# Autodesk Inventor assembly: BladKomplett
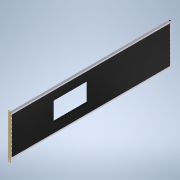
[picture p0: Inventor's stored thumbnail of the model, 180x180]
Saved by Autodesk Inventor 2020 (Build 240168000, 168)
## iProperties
Created: 2019-06
Part Number: BladKomplett
Document SubType Name: Assembly
Designer: cl
Author: cl
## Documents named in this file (4)
- G:\AutoCad\Carl Lund\4-delad\4-Del-0Glas-In\Parts\BladKomplett.iam
- G:\AutoCad\Carl Lund\4-delad\4-Del-0Glas-In\Parts\Blad.ipt
- G:\AutoCad\Carl Lund\4-delad\4-Del-0Glas-In\Parts\AluKarmBlad.ipt
- G:\AutoCad\Carl Lund\4-delad\4-Del-0Glas-In\Styrande(4-Del-0Glas-In).iam
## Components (2 placed, 2 different names)
1. Blad:1 — Flush:1, Flush:2
2. AluKarmBlad:1 — Flush:1, Flush:2
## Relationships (2: Flush 2)
- Flush:1: Blad:1 ↔ AluKarmBlad:1
- Flush:2: Blad:1 ↔ AluKarmBlad:1
## Named parameters: BladBredd = 987.5 mm
